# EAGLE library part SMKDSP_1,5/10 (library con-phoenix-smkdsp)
Printklemme, Nennstrom: 17,5 A, Bemessungsspannung: 250 V, Raster: 5,0 mm Source: http://eshop.phoenixcontact.de .. 1733415.pdf
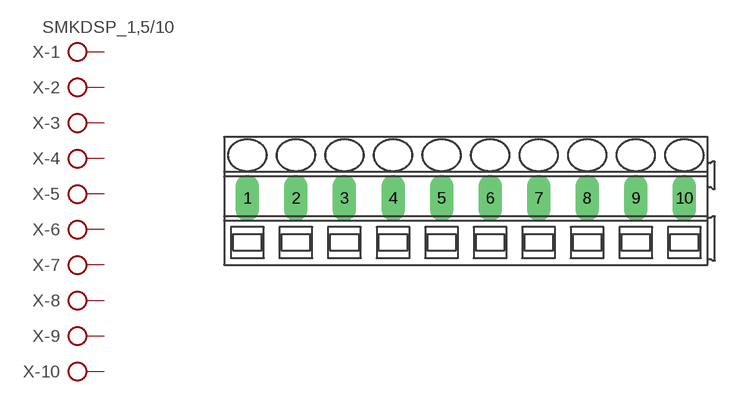
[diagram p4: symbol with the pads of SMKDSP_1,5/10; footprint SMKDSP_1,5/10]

Designator prefix X; gates -1=KLV -2=KL -3=KL -4=KL -5=KL -6=KL -7=KL -8=KL -9=KL -10=KL

## SMKDSP_1,5/10 (MF: FARNELL; MPN: 1733651; OC_FARNELL: 3041293; OC_NEWARK: 71C4134)  [SMKDSP_1,5/10]
1  -1:KL  pas
2  -2:KL  pas
3  -3:KL  pas
4  -4:KL  pas
5  -5:KL  pas
6  -6:KL  pas
7  -7:KL  pas
8  -8:KL  pas
9  -9:KL  pas
10  -10:KL  pas

## Footprint SMKDSP_1,5/10 (pad centres in mm)
Printklemme, Nennstrom: 17,5 A, Bemessungsspannung: 250 V, Raster: 5,0 mm Source: http://eshop.phoenixcontact.de .. 1733415.pdf
drill 1.6 pad 1.8 long: 1 -2.5,0; 2 2.5,0; 3 7.5,0; 4 12.5,0; 5 17.5,0; 6 22.5,0; 7 27.5,0; 8 32.5,0; 9 37.5,0; 10 42.5,0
